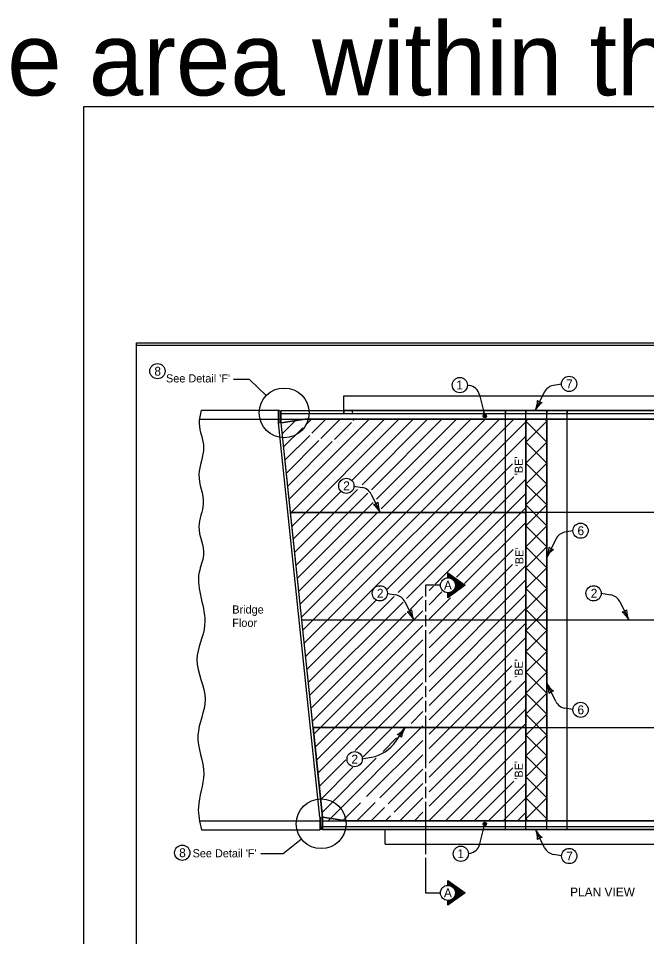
# Model space of a CAD drawing. Extents: x 10028 to 81668, y 6395 to 11634.
# Drawn here: x 13500 to 14736, y 8776 to 10582 of the extents above; entities that cross this region are included whole.
import ezdxf

# ---------------------------------------------------------------- set-up
doc = ezdxf.new("R2010")
doc.units = 0
for name, color, linetype in [('Default', 7, 'Continuous'), ('dsnCellElements', 7, 'Continuous'), ('dsnstdblockInterim', 7, 'Continuous'), ('dsnStdDimension', 7, 'Continuous'), ('dsnStdTextLabel', 7, 'Continuous'), ('ShtPlotIdentification', 7, 'Continuous')]:
    doc.layers.add(name, color=color, linetype=linetype)

msp = doc.modelspace()

# ---------------------------------------------------------------- linework, layer by layer
at = {"layer": 'Default'}
msp.add_lwpolyline([(13732.5, 9944), (16867.5, 9944), (16867.5, 7924), (13732.5, 7924)], close=True, dxfattribs=at)
at = {"layer": 'dsnCellElements'}
for p, q in [((13954.8, 9871.9), (13923.3, 9871.9)), ((13987.6, 9840.1), (13954.8, 9871.9)), ((14534.4, 9846.6), (14516.7, 9810.6)), ((14568.2, 9862.6), (14552.3, 9859.9)), ((14406.9, 9841.7), (14417.3, 9799.9)), ((14156.6, 9810.6), (14140.2, 9810.6)), ((14140.2, 9810.6), (14140.2, 9804.7)), ((14414.6, 9810.6), (14156.6, 9810.6)), ((14416.1, 9804.7), (14414.6, 9810.6)), ((14458.1, 9810.6), (14414.6, 9810.6)), ((14414.6, 9810.6), (14416.1, 9804.7)), ((14458.1, 9804.7), (14458.1, 9810.6)), ((14498.1, 9810.6), (14458.1, 9810.6)), ((14458.1, 9810.6), (14458.1, 9804.7)), ((14498.1, 9804.7), (14498.1, 9810.6)), ((14498.1, 9810.6), (14498.1, 9804.7)), ((14539.3, 9810.6), (14516.7, 9810.6)), ((14539.3, 9804.7), (14539.3, 9810.6)), ((14579.3, 9810.6), (14539.3, 9810.6)), ((14539.3, 9810.6), (14539.3, 9804.7)), ((14579.3, 9804.7), (14579.3, 9810.6)), ((14891.7, 9810.6), (14579.3, 9810.6)), ((14579.3, 9810.6), (14579.3, 9804.7)), ((14140.2, 9804.7), (14157.6, 9804.7)), ((14157.6, 9804.7), (14416.1, 9804.7)), ((14416.1, 9804.7), (14458.1, 9804.7)), ((14458.1, 9804.7), (14498.1, 9804.7)), ((14498.1, 9804.7), (14539.3, 9804.7)), ((14539.3, 9804.7), (14579.3, 9804.7)), ((14579.3, 9804.7), (14891.7, 9804.7)), ((14160.1, 9662.1), (14176, 9659.5)), ((14193.9, 9646.2), (14211.6, 9610.1)), ((14079.8, 9187.2), (14035.4, 9610.1)), ((14035.4, 9610.1), (14498.1, 9610.1)), ((14498.1, 9610.1), (14498.1, 9610.1)), ((14498.1, 9610.1), (14498.1, 9187.2)), ((14557.1, 9557.9), (14539.3, 9521.8)), ((14590.8, 9573.8), (14575, 9571.2)), ((14225.9, 9450.8), (14242.2, 9448)), ((14646.4, 9451.1), (14665, 9448)), ((14260.1, 9434.7), (14277.9, 9398.7)), ((14682.9, 9434.7), (14700.7, 9398.7)), ((14557.1, 9238.3), (14539.3, 9274.4)), ((14590.8, 9222.3), (14575, 9225)), ((14498.1, 9187.2), (14079.8, 9187.2)), ((14079.8, 9187.2), (15420.4, 9187.2)), ((14242.2, 9159.8), (14260.6, 9187.2)), ((14498.1, 9187.2), (14498.1, 9187.2)), ((14176.4, 9125.3), (14194.3, 9128.5)), ((14407.5, 8958), (14417.3, 8997.4)), ((14534.7, 8950.7), (14516.9, 8986.7)), ((14057.2, 8967.3), (14020.9, 8938.6)), ((14020.9, 8938.6), (13977.1, 8938.6)), ((14568.4, 8934.7), (14552.6, 8937.4))]:
    msp.add_line(p, q, dxfattribs=at)
for points in [[(14516.7, 9810.6), (14516.7, 9810.6), (14498.1, 9810.6)], [(14330.1, 9466.9), (14300.7, 9466.9), (14300.7, 9444.9)], [(14300.7, 9437.5), (14300.7, 9415.5)], [(14300.7, 9408.2), (14300.7, 9386.1)], [(14300.7, 9378.8), (14300.7, 9276)], [(14300.7, 9268.7), (14300.7, 9246.6)], [(14300.7, 9239.3), (14300.7, 9217.3)], [(14300.7, 9209.9), (14300.7, 9107.1)], [(14300.7, 9099.8), (14300.7, 9077.8)], [(14300.7, 9070.4), (14300.7, 9048.4)], [(14300.7, 9041), (14300.7, 8938.2)], [(14300.7, 8930.9), (14300.7, 8908.9)], [(14300.7, 8911.3), (14300.7, 8861.8), (14330.1, 8861.8)]]:
    msp.add_lwpolyline(points, dxfattribs=at)
msp.add_circle((14022.7, 9806), 49, dxfattribs=at)
for centre, radius, start, end in [((14383.1, 9835.8), 24.5, 13.9846, 80.0697), ((14556.4, 9835.8), 24.5, 99.5323, 153.7542), ((14108.9, 9799.6), 49, 6.0235, 12.9992), ((14108.9, 9799.6), 49, 6.0235, 12.9992), ((14478.7, 9829.3), 42.3, 333.7545, 333.7562), ((14554.6, 9791.9), 42.3, 153.7527, 153.7545), ((14171.9, 9635.3), 24.5, 26.2458, 80.4677), ((14579, 9547), 24.5, 99.5323, 153.7542), ((14238.1, 9423.9), 24.5, 26.2458, 80.4677), ((14661, 9423.9), 24.5, 26.2458, 80.4677), ((14579, 9249.1), 24.5, 206.2458, 260.4677), ((14181.3, 9200.8), 73.4, 280.1875, 326.0921), ((14383.7, 8963.9), 24.5, 279.5445, 346.0154), ((14556.7, 8961.5), 24.5, 206.2458, 260.4677)]:
    msp.add_arc(centre, radius, start, end, dxfattribs=at)
at = {"layer": 'dsnstdblockInterim'}
msp.add_lwpolyline([(13732.5, 9939), (16867.5, 9939), (16867.5, 7929), (13732.5, 7929)], close=True, dxfattribs=at)
at = {"layer": 'dsnStdDimension'}
msp.add_lwpolyline([(13628, 7824.5), (16972, 7824.5), (16972, 10408.5), (13628, 10408.5)], close=True, dxfattribs=at)
at = {"layer": 'ShtPlotIdentification'}
for p, q in [((14383.3, 9860.6), (14387.3, 9859.9)), ((14140.2, 9839.9), (14927, 9839.9)), ((14140.2, 9804.7), (14140.2, 9839.9)), ((13859.8, 9811.3), (14011.5, 9811.3)), ((14011.5, 9786.3), (14011.5, 9811.3)), ((14014.2, 9810.2), (14011.5, 9811.3)), ((14014.2, 9810.2), (14016.8, 9810.6)), ((14014.2, 9810.2), (14014.2, 9787.4)), ((14016.8, 9810.6), (14891.7, 9810.6)), ((14016.8, 9786.3), (14016.8, 9810.6)), ((14016.8, 9810.6), (14140.2, 9810.6)), ((14016.8, 9786.3), (14016.8, 9810.6)), ((14016.8, 9786.3), (14016.8, 9810.6)), ((14140.2, 9810.6), (14140.2, 9804.7)), ((14458.1, 8986.7), (14458.1, 9810.6)), ((14498.1, 8986.7), (14498.1, 9810.6)), ((14539.3, 8986.7), (14539.3, 9810.6)), ((14579.3, 8986.7), (14579.3, 9810.6)), ((13856.3, 9793.7), (14011.5, 9793.7)), ((14011.5, 9793.7), (14063.8, 9793.7)), ((14016.8, 9786.3), (14063.8, 9793.7)), ((14063.8, 9793.7), (14016.8, 9786.3)), ((14032.6, 9636.4), (14189.9, 9793.7)), ((14035.5, 9609.1), (14220.1, 9793.7)), ((14038.2, 9583.5), (14248.3, 9793.7)), ((14054.3, 9429.7), (14418.3, 9793.7)), ((14057, 9404.1), (14446.6, 9793.7)), ((14059.7, 9378.5), (14474.8, 9793.7)), ((14063.8, 9793.7), (14498.1, 9793.7)), ((14063.8, 9793.7), (15247.1, 9793.7)), ((14891.7, 9793.7), (14063.8, 9793.7)), ((14063.8, 9793.7), (14063.8, 9793.7)), ((14064.4, 9781.5), (14076.5, 9793.7)), ((14077.2, 9766.1), (14104.8, 9793.7)), ((14094.8, 9755.4), (14133.1, 9793.7)), ((14140.2, 9804.7), (14891.7, 9804.7)), ((14156, 9673), (14276.6, 9793.7)), ((14158.8, 9791.1), (14161.4, 9793.7)), ((14176, 9664.8), (14304.9, 9793.7)), ((14194.5, 9655), (14333.2, 9793.7)), ((14204.7, 9636.6), (14361.7, 9793.7)), ((14213.4, 9617.1), (14390, 9793.7)), ((14498.1, 9793.7), (14498.1, 9610.1)), ((14498.1, 9793.7), (14539.3, 9793.7)), ((14498.1, 9003.6), (14498.1, 9793.7)), ((14502.3, 9793.7), (14498.1, 9789.6)), ((14535.2, 9793.7), (14539.3, 9789.6)), ((14539.3, 9793.7), (14891.7, 9793.7)), ((14539.3, 9003.6), (14539.3, 9793.7)), ((14539.3, 9793.7), (14539.3, 9003.6)), ((14011.5, 9786.3), (14014.2, 9787.4)), ((14093, 9011), (14011.5, 9786.3)), ((14016.8, 9786.4), (14014.2, 9787.4)), ((14035.4, 9610.1), (14016.8, 9786.3)), ((14098.3, 9011), (14016.8, 9786.3)), ((14019.1, 9764.6), (14045.4, 9790.8)), ((14021.8, 9739), (14059.6, 9776.8)), ((14062.4, 9352.9), (14498.1, 9788.7)), ((14121.5, 9753.8), (14155.1, 9787.4)), ((14498.1, 9789.6), (14539.3, 9748.4)), ((14539.3, 9789.6), (14498.1, 9748.4)), ((14024.5, 9713.4), (14073, 9761.9)), ((14065.1, 9327.3), (14498.1, 9760.4)), ((14027.2, 9687.8), (14091, 9751.6)), ((14029.9, 9662.2), (14117.5, 9749.8)), ((14498.1, 9748.4), (14539.3, 9707.3)), ((14539.3, 9748.4), (14498.1, 9707.3)), ((14224.1, 9458.1), (14471.8, 9705.8)), ((14498.1, 9707.3), (14539.3, 9666.1)), ((14539.3, 9707.3), (14498.1, 9666.1)), ((14247, 9452.7), (14474.4, 9680.1)), ((14263.3, 9440.7), (14498.1, 9675.5)), ((14498.1, 9666.1), (14539.3, 9625)), ((14539.3, 9666.1), (14498.1, 9625)), ((14040.8, 9557.9), (14134.7, 9651.8)), ((14043.5, 9532.3), (14166.8, 9655.6)), ((14046.2, 9506.7), (14187.6, 9648.1)), ((14319.9, 9469), (14498.1, 9647.3)), ((14048.9, 9480.9), (14198, 9630)), ((14051.6, 9455.3), (14207.3, 9611)), ((14361.8, 9482.6), (14498.1, 9619)), ((14498.1, 9625), (14539.3, 9583.8)), ((14539.3, 9625), (14498.1, 9583.8)), ((14498.1, 9610.1), (14035.4, 9610.1)), ((15420.4, 9610.1), (14035.4, 9610.1)), ((14377.7, 9470.3), (14498.1, 9590.7)), ((14498.1, 9583.8), (14539.3, 9542.7)), ((14539.3, 9583.8), (14498.1, 9542.7)), ((14498.1, 9542.7), (14539.3, 9501.5)), ((14539.3, 9542.7), (14498.1, 9501.5)), ((14307.7, 9371.9), (14473, 9537.2)), ((14307.7, 9343.7), (14471.8, 9507.8)), ((14307.7, 9315.4), (14498.1, 9505.8)), ((14498.1, 9501.5), (14539.3, 9460.4)), ((14539.3, 9501.5), (14498.1, 9460.4)), ((14307.7, 9287.1), (14498.1, 9477.6)), ((14307.7, 9456.8), (14316.3, 9465.4)), ((14307.7, 9428.5), (14333.2, 9454.1)), ((14307.7, 9258.8), (14498.1, 9449.3)), ((14498.1, 9460.4), (14539.3, 9419.2)), ((14539.3, 9460.4), (14498.1, 9419.2)), ((14067.8, 9301.8), (14203.9, 9437.9)), ((14070.5, 9276.2), (14239, 9444.7)), ((14073.1, 9250.6), (14256.6, 9434)), ((14270.5, 9419.6), (14295.5, 9444.6)), ((14307.7, 9400.2), (14349.7, 9442.2)), ((14078.5, 9199.4), (14295.5, 9416.4)), ((14307.7, 9230.5), (14498.1, 9421)), ((14498.1, 9419.2), (14539.3, 9378.1)), ((14539.3, 9419.2), (14498.1, 9378.1)), ((14057.6, 9398.7), (14498.1, 9398.7)), ((14075.8, 9225), (14262.8, 9412)), ((14498.1, 9398.7), (15950.4, 9398.7)), ((14081.2, 9173.8), (14295.5, 9388.1)), ((14307.7, 9202.2), (14498.1, 9392.7)), ((14498.1, 9378.1), (14539.3, 9336.9)), ((14539.3, 9378.1), (14498.1, 9336.9)), ((14083.9, 9148.2), (14295.5, 9359.8)), ((14307.7, 9173.9), (14498.1, 9364.4)), ((14086.6, 9122.6), (14295.5, 9331.5)), ((14498.1, 9336.9), (14539.3, 9295.8)), ((14539.3, 9336.9), (14498.1, 9295.8)), ((14307.7, 9145.7), (14470.6, 9308.6)), ((14089.3, 9097), (14295.5, 9303.2)), ((14498.1, 9295.8), (14539.3, 9254.6)), ((14539.3, 9295.8), (14498.1, 9254.6)), ((14162.7, 9142.1), (14295.5, 9274.9)), ((14307.7, 9089.1), (14498.1, 9279.6)), ((14307.7, 9117.4), (14469.5, 9279.2)), ((14307.7, 9060.8), (14498.1, 9251.3)), ((14498.1, 9254.6), (14539.3, 9213.5)), ((14539.3, 9254.6), (14498.1, 9213.5)), ((14178.1, 9129.2), (14295.5, 9246.7)), ((14272.3, 9195.1), (14295.5, 9218.4)), ((14307.7, 9032.5), (14498.1, 9223)), ((14498.1, 9213.5), (14539.3, 9172.3)), ((14539.3, 9213.5), (14498.1, 9172.3)), ((14098.3, 9011), (14079.8, 9187.2)), ((14079.8, 9187.2), (14297.9, 9187.2)), ((14498.1, 9187.2), (14079.8, 9187.2)), ((14079.8, 9187.2), (14098.3, 9011)), ((14109.1, 9003.6), (14295.5, 9190.1)), ((14304.7, 9187.2), (14498.1, 9187.2)), ((14307, 9003.6), (14498.1, 9194.7)), ((14498.1, 9187.2), (14498.1, 9003.6)), ((14498.1, 9003.6), (14498.1, 9187.2)), ((14184.9, 9051.2), (14295.5, 9161.8)), ((14217.3, 9140.1), (14243.6, 9166.5)), ((14340.1, 9003.6), (14498.1, 9161.7)), ((14498.1, 9172.3), (14539.3, 9131.2)), ((14539.3, 9172.3), (14498.1, 9131.2)), ((14092, 9071.4), (14144.2, 9123.7)), ((14097.4, 9020.2), (14203.7, 9126.6)), ((14210.8, 9048.8), (14295.5, 9133.5)), ((14498, 9134.9), (14498.1, 9134.9)), ((14498.1, 9131.2), (14539.3, 9090)), ((14539.3, 9131.2), (14498.1, 9090)), ((14094.7, 9045.8), (14157.9, 9109)), ((14227.3, 9037), (14295.5, 9105.2)), ((14368.4, 9003.6), (14472.5, 9107.7)), ((14498.1, 9090), (14539.3, 9048.9)), ((14539.3, 9090), (14498.1, 9048.9)), ((14239.1, 9020.5), (14295.5, 9076.9)), ((14396.7, 9003.6), (14474.6, 9081.6)), ((14424.9, 9003.6), (14498.1, 9076.8)), ((14137.3, 9003.6), (14172.9, 9039.2)), ((14165.6, 9003.6), (14201.9, 9039.9)), ((14250.5, 9003.6), (14295.5, 9048.7)), ((14453.4, 9003.6), (14498.1, 9048.3)), ((14498.1, 9048.9), (14539.3, 9007.7)), ((14539.3, 9048.9), (14498.1, 9007.7)), ((14193.9, 9003.6), (14219.8, 9029.6)), ((14278.8, 9003.6), (14295.5, 9020.4)), ((14481.7, 9003.6), (14498.1, 9020.1)), ((13856.3, 9003.6), (14093, 9003.6)), ((14093, 9011), (14093, 8986)), ((14093, 9011), (14095.7, 9009.9)), ((14098.3, 9010.9), (14095.7, 9009.9)), ((14095.7, 8987.1), (14095.7, 9009.9)), ((14145.3, 9003.6), (14098.3, 9011)), ((14098.3, 9011), (14098.3, 9011)), ((14098.3, 9011), (14145.3, 9003.6)), ((14145.3, 9003.6), (14098.3, 9011)), ((14098.3, 9011), (14098.3, 9003.6)), ((14098.3, 9011), (14098.3, 8986.7)), ((14098.3, 9011), (14098.3, 8986.7)), ((14098.3, 9003.6), (14098.3, 8992.6)), ((14098.3, 9003.6), (14145.3, 9003.6)), ((14145.3, 9003.6), (15247.1, 9003.6)), ((14498.1, 9003.6), (14145.3, 9003.6)), ((14145.3, 9003.6), (14498.1, 9003.6)), ((14891.7, 9003.6), (14145.3, 9003.6)), ((14145.3, 9003.6), (14145.3, 9003.6)), ((14222.2, 9003.6), (14232.2, 9013.6)), ((14498.1, 9007.7), (14502.3, 9003.6)), ((14539.3, 9003.6), (14498.1, 9003.6)), ((14539.3, 9007.7), (14535.2, 9003.6)), ((14891.7, 9003.6), (14539.3, 9003.6)), ((13860, 8986), (14093, 8986)), ((14095.7, 8987.1), (14093, 8986)), ((14095.7, 8987.1), (14098.3, 8986.7)), ((14098.3, 8992.6), (14221.7, 8992.6)), ((14098.3, 8986.7), (14891.7, 8986.7)), ((14221.7, 8992.6), (14891.7, 8992.6)), ((14221.7, 8957.4), (14221.7, 8986)), ((14221.7, 8957.4), (14927, 8957.4)), ((14385.2, 8939.3), (14389.3, 8940))]:
    msp.add_line(p, q, dxfattribs=at)
for points in [[(14016.8, 9804.7), (15247.1, 9804.7), (15420.4, 9786.3)], [(14417, 9803), (14418.2, 9802.5), (14420, 9802), (14420.3, 9800.1), (14420.1, 9798.5), (14418.9, 9797.1), (14417.2, 9797.2), (14415.4, 9797.5), (14414.5, 9798.9), (14414.4, 9800.4), (14415.4, 9802.4), (14416.8, 9802.6), (14418.6, 9802.1), (14420, 9801), (14420, 9799.2), (14418.8, 9797.9), (14417.2, 9797.7), (14415.4, 9798.1), (14415.1, 9799.1), (14414.8, 9800.3), (14415.6, 9801.8), (14416.9, 9801.7), (14418.4, 9801.5), (14419.5, 9800.7), (14419, 9799.2), (14417.8, 9798.3), (14416.3, 9798.2), (14415.9, 9799.1), (14415.5, 9800), (14416.2, 9801.2), (14417.3, 9801.4), (14418.3, 9800.9), (14418.4, 9799.8), (14417.9, 9799), (14416.8, 9798.7), (14416.4, 9799.1), (14416.1, 9799.8), (14416.6, 9800.6), (14417.3, 9800.8), (14418, 9800.4), (14417.9, 9799.8), (14417.4, 9799.4), (14416.7, 9799.4), (14416.7, 9799.9), (14417.3, 9800.2)], [(14344.8, 9481.6), (14344.8, 9491.4), (14379, 9466.9), (14344.8, 9442.4), (14344.8, 9452.2)], [(14345.7, 9451.3), (14345.6, 9444.2), (14377.2, 9466.9), (14345.6, 9489.8), (14345.8, 9482.3), (14347.1, 9481.9), (14346.6, 9487.4), (14375.1, 9466.9), (14346.6, 9446.2), (14346.9, 9451.4), (14347.9, 9451.6), (14347.8, 9448.2), (14373.2, 9467), (14347.8, 9484.9), (14348.3, 9481.8), (14349.4, 9481.5), (14349.2, 9482.6), (14371, 9466.7), (14348.9, 9450), (14350, 9451.9), (14369.1, 9466.5), (14357.4, 9475.9), (14358.1, 9474.2), (14367.1, 9466.5), (14358.4, 9459.8), (14359.2, 9461.6), (14365.3, 9466.3), (14359.2, 9471.5), (14359.8, 9469.2), (14363.7, 9466.2), (14359.7, 9463.1), (14360, 9464.7), (14362.2, 9466.1), (14360, 9467.4), (14360.2, 9466), (14360.9, 9466.1)], [(14098.3, 8992.6), (15247.1, 8992.6), (15420.4, 9011)], [(14417, 9000.6), (14418.2, 9000), (14420, 8999.5), (14420.3, 8997.6), (14420.1, 8996), (14418.9, 8994.6), (14417.2, 8994.7), (14415.4, 8995), (14414.5, 8996.4), (14414.4, 8997.9), (14415.4, 8999.9), (14416.8, 9000.1), (14418.6, 8999.6), (14420, 8998.5), (14420, 8996.8), (14418.8, 8995.4), (14417.2, 8995.2), (14415.4, 8995.6), (14415.1, 8996.6), (14414.8, 8997.8), (14415.6, 8999.3), (14416.9, 8999.3), (14418.4, 8999), (14419.5, 8998.2), (14419, 8996.7), (14417.8, 8995.8), (14416.3, 8995.8), (14415.9, 8996.6), (14415.5, 8997.5), (14416.2, 8998.7), (14417.3, 8998.9), (14418.3, 8998.4), (14418.4, 8997.3), (14417.9, 8996.5), (14416.8, 8996.2), (14416.4, 8996.7), (14416.1, 8997.3), (14416.6, 8998.2), (14417.3, 8998.3), (14418, 8997.9), (14417.9, 8997.3), (14417.4, 8996.9), (14416.7, 8997), (14416.7, 8997.5), (14417.3, 8997.7)], [(14344.8, 8876.5), (14344.8, 8886.3), (14379, 8861.8), (14344.8, 8837.4), (14344.8, 8847.1)], [(14345.7, 8846.2), (14345.6, 8839.1), (14377.2, 8861.8), (14345.6, 8884.7), (14345.8, 8877.2), (14347.1, 8876.8), (14346.6, 8882.3), (14375.1, 8861.8), (14346.6, 8841.1), (14346.9, 8846.3), (14347.9, 8846.5), (14347.8, 8843.1), (14373.2, 8861.9), (14347.8, 8879.8), (14348.3, 8876.8), (14349.4, 8876.5), (14349.2, 8877.5), (14371, 8861.6), (14348.9, 8844.9), (14350, 8846.8), (14369.1, 8861.5), (14357.4, 8870.8), (14358.1, 8869.1), (14367.1, 8861.4), (14358.4, 8854.7), (14359.2, 8856.5), (14365.3, 8861.2), (14359.2, 8866.4), (14359.8, 8864.1), (14363.7, 8861.1), (14359.7, 8858), (14360, 8859.6), (14362.2, 8861), (14360, 8862.4), (14360.2, 8861), (14360.9, 8861)]]:
    msp.add_lwpolyline(points, dxfattribs=at)
msp.add_lwpolyline([(14098.3, 8992.6), (14891.7, 8992.6), (14891.7, 8986.7), (14098.3, 8986.7)], close=True, dxfattribs=at)
for centre, radius in [((13773.6, 9888.1), 15), ((14368.3, 9860.8), 15), ((14583.2, 9863.1), 15), ((14417.3, 9799.9), 3.43), ((14145.1, 9662.6), 15), ((14605.8, 9574.3), 15), ((14344.8, 9466.9), 14.7), ((14210.9, 9451.1), 15), ((14631.4, 9451.1), 15), ((14605.8, 9221.9), 15), ((14161.4, 9124.8), 15), ((14095.5, 8997.8), 49), ((14417.3, 8997.4), 3.43), ((13822.4, 8940.8), 15), ((14370.2, 8938.8), 15), ((14583.4, 8934.3), 15), ((14344.8, 8861.8), 14.7)]:
    msp.add_circle(centre, radius, dxfattribs=at)
for centre, radius, start, end in [((14478.7, 9829.3), 42.3, 333.7545, 1.8269), ((14532.3, 9842.4), 16.3, 226.0211, 261.4878), ((14554.6, 9791.9), 42.3, 125.682, 153.7545), ((14196, 9641.9), 16.3, 278.5122, 313.9789), ((14249.6, 9628.8), 42.3, 178.1731, 206.2455), ((14173.7, 9591.4), 42.3, 26.2455, 54.318), ((14501.4, 9540.5), 42.3, 333.7545, 1.8269), ((14555, 9553.6), 16.3, 226.0211, 261.4878), ((14577.2, 9503.1), 42.3, 125.682, 153.7545), ((14262.2, 9430.4), 16.3, 278.5122, 313.9789), ((14239.9, 9380), 42.3, 26.2455, 54.318), ((14315.8, 9417.3), 42.3, 178.1731, 206.2455), ((14685, 9430.4), 16.3, 278.5122, 313.9789), ((14662.8, 9380), 42.3, 26.2455, 54.318), ((14738.6, 9417.3), 42.3, 178.1731, 206.2455), ((14577.2, 9293), 42.3, 206.2455, 234.318), ((14501.4, 9255.7), 42.3, 358.1731, 26.2455), ((14555, 9242.6), 16.3, 98.5122, 133.9789), ((14225.6, 9210.8), 42.3, 298.0176, 326.0901), ((14225.6, 9210.8), 42.3, 298.0176, 326.0901), ((14295.7, 9163.6), 42.3, 146.0901, 174.1626), ((14295.7, 9163.6), 42.3, 146.0901, 174.1626), ((14240.9, 9157.8), 16.3, 38.3568, 73.8235), ((14240.9, 9157.8), 16.3, 38.3568, 73.8235), ((14554.8, 9005.4), 42.3, 206.2455, 234.318), ((14479, 8968), 42.3, 358.1731, 26.2455), ((14532.6, 8954.9), 16.3, 98.5122, 133.9789)]:
    msp.add_arc(centre, radius, start, end, dxfattribs=at)
msp.add_spline([(13859.8, 9811.3), (13855.6, 9784.9), (13864.3, 9738.2), (13855, 9684.6), (13863.7, 9627.3), (13855, 9582.4), (13864.3, 9526.4), (13855.6, 9492.7), (13866.4, 9388.7), (13851.2, 9321.2), (13867.3, 9242.3), (13853.1, 9172), (13864.5, 9095.9), (13854, 9030.3), (13860, 8986)], degree=3, dxfattribs=at)

# ---------------------------------------------------------------- texts
at = {"layer": 'dsnCellElements'}
for s, height, p in [('8', 17.5, (13767.5, 9879.3)), ("See Detail 'F'", 16, (13790.4, 9866)), ('1', 17.5, (14361.1, 9852.1)), ('7', 17.5, (14577.2, 9854.3)), ('2', 17.5, (14138.9, 9653.9)), ('6', 17.5, (14599.7, 9565.5)), ('A', 17.5, (14337, 9458.2)), ('2', 17.5, (14205.1, 9442.4)), ('2', 17.5, (14625.7, 9442.4)), ('Bridge', 16, (13920.7, 9411.3)), ('Floor', 16, (13920.7, 9385.1)), ('6', 17.5, (14599.7, 9213.1)), ('2', 17.5, (14155.1, 9116.1)), ('8', 17.5, (13816.3, 8932)), ("See Detail 'F'", 16, (13842.7, 8931.7)), ('1', 17.5, (14363.6, 8930.1)), ('7', 17.5, (14577.5, 8925.5)), ('A', 17.5, (14337, 8853.1)), ('PLAN VIEW', 17.5, (14585.2, 8854.7))]:
    msp.add_text(s, height=height, dxfattribs=at).set_placement(p)
for p in [(14492.1, 9683.5), (14493.4, 9504.2), (14492.1, 9285), (14492.1, 9084.5)]:
    msp.add_text("'BE'", height=16, rotation=90, dxfattribs=at).set_placement(p)
at = {"layer": 'dsnStdTextLabel'}
msp.add_text('The boxes below encompass the usable area within the print border.', height=144, dxfattribs=at).set_placement((10149.1, 10430.6))

doc.saveas('drawing.dxf')
